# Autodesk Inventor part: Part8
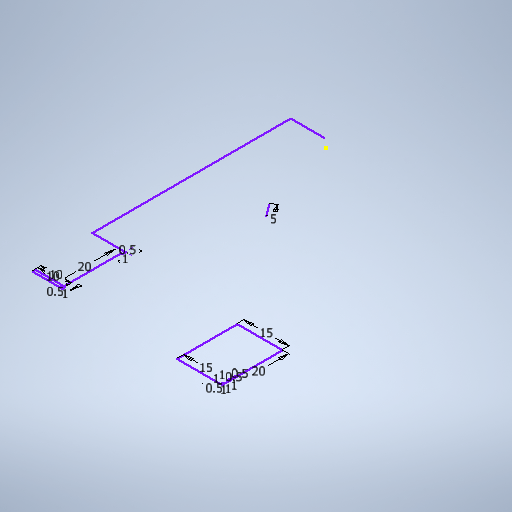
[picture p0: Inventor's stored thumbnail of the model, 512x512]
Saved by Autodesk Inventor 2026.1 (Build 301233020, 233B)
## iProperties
Created: 2026-11
Part Number: Part8
Material: Generic
Document SubType Name: Modeling
Designer: hp
Density: 1 g/cm^3
Appearance: Default
Author: hp
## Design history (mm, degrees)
sketch "Sketch1"
  geometry: L1 (13.51, 83.972)-(3.51, 83.972); L2 (3.51, 83.972)-(3.51, 82.972); L3 (3.51, 82.972)-(13.51, 82.972); L4 (13.51, 82.972)-(13.51, 83.972); L5 (-9.401, 29.276)-(-6.474, 25.222); L6 (3.51, 83.972)-(4.01, 83.972); L7 (4.01, 83.972)-(4.01, 63.972); L8 (4.01, 63.972)-(3.51, 63.972); L9 (3.51, 63.972)-(3.51, 62.972); L10 (3.51, 62.972)-(14.588, 62.972); L11 (14.588, 62.972)-(14.588, -2.847); L12 (14.588, -2.847)-(3.349, -2.847); L13 (-35.649, 85.106)-(-50.649, 85.106); L14 (-50.649, 85.106)-(-50.649, 65.106); L15 (-50.649, 65.106)-(-35.649, 65.106); L16 (-35.649, 65.106)-(-35.649, 85.106); L17 (-50.649, 85.106)-(-50.149, 85.106); L18 (-50.149, 85.106)-(-50.149, 84.106); L19 (-50.149, 84.106)-(-50.649, 84.106); L20 (-50.649, 84.106)-(-50.649, 83.106); L21 (-50.649, 83.106)-(-50.149, 83.106); L22 (-50.149, 83.106)-(-50.149, 82.106); L23 (-50.149, 82.106)-(-50.649, 82.106); L24 (-50.649, 82.106)-(-50.649, 81.106); L25 (-50.649, 81.106)-(-50.149, 81.106); L26 (-50.149, 81.106)-(-50.149, 80.106); L27 (-50.149, 80.106)-(-50.649, 80.106); 1 further point
  constraints: 54 end point, 13 perpendicular, 9 point on line, 3 horizontal, 1 parallel, 1 vertical
  dimensions: "d0" = 10 distance of L1.start L1.end; "d1" = 1 distance of L1.end L2.end; "d2" = 10 distance of L2.end L3.end; "d3" = 5 distance of L5.start L5.end; "d4" = 0.5 distance of L1.end L6.end; "d5" = 20 distance of L6.end L7.end; "d6" = 0.5 distance of L7.end L8.end; "d7" = 1 distance of L8.end L9.end; "d8" = 15 distance of L13.start L13.end; "d9" = 20 distance of L13.end L14.end; "d10" = 15 distance of L14.end L15.end; "d11" = 0.5 distance of L13.end L17.end; "d12" = 1 distance of L17.end L18.end; "d13" = 1 distance of L19.end L20.end; "d14" = 0.5 distance of L20.end L21.end; "d15" = 1 distance of L21.end L22.end; "d16" = 1 distance of L23.end L24.end; "d17" = 0.5 distance of L24.end L25.end; "d18" = 1 distance of L25.end L26.end
